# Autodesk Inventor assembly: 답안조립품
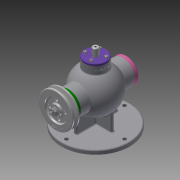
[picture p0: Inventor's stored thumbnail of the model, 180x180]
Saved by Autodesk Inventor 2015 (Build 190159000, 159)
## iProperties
Created: 2020-08
Part Number: 답안조립품
Document SubType Name: Assembly
Designer: now
Author: now
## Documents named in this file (18)
- C:\Users\now\Desktop\700806V1040\답안조립품.iam
- C:\Users\now\Desktop\700806V1040\Ű 3x3x12.ipt
- C:\Users\now\Desktop\700806V1040\V-벨트풀리.ipt
- C:\Users\now\Desktop\700806V1040\너트 M8.ipt
- C:\Users\now\Desktop\700806V1040\뒤커버.ipt
- C:\Users\now\Desktop\700806V1040\멈춤링 15x1.ipt
- C:\Users\now\Desktop\700806V1040\멈춤링 35x1.6.ipt
- 멈춤링 35x1.6.ipt
- C:\Users\now\Desktop\700806V1040\베어링 6202.ipt
- 베어링 6202.ipt
- C:\Users\now\Desktop\700806V1040\본체.ipt
- C:\Users\now\Desktop\700806V1040\볼트 M4.ipt
- C:\Users\now\Desktop\700806V1040\상부커버.ipt
- C:\Users\now\Desktop\700806V1040\슬라이드.ipt
- C:\Users\now\Desktop\700806V1040\앞커버.ipt
- C:\Users\now\Desktop\700806V1040\오일 실 15 30 7.ipt
- C:\Users\now\Desktop\700806V1040\칼라.ipt
- C:\Users\now\Desktop\700806V1040\편심축.ipt
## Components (2 placed, 2 different names)
1. Ű 3x3x12:1 — 각도:1, 각도:2
2. V-벨트풀리:1 — 각도:2
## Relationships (2: Angle 2)
- 각도:1 [Angle]: Ű 3x3x12:1
- 각도:2 [Angle]: Ű 3x3x12:1 ↔ V-벨트풀리:1
